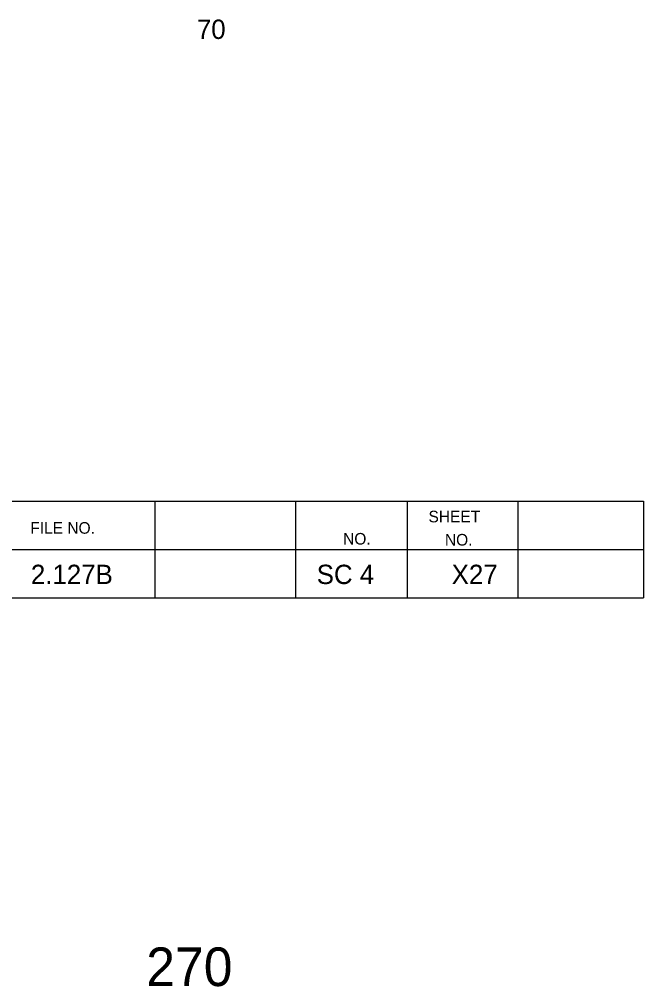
# Model space of a CAD drawing. Extents: x 1000 to 1162, y 999 to 8520.
# Drawn here: x 1145.41 to 1161.56, y 4079.99 to 4105.01 of the extents above; entities that cross this region are included whole.
import ezdxf

# ---------------------------------------------------------------- set-up
doc = ezdxf.new("R2010")
doc.units = 0
for name, color, linetype in [('Level 11', 7, 'Continuous'), ('Level 20', 7, 'Continuous'), ('Level 3', 7, 'Continuous'), ('Level 56', 7, 'Continuous')]:
    doc.layers.add(name, color=color, linetype=linetype)

msp = doc.modelspace()

# ---------------------------------------------------------------- linework, layer by layer
at = {"layer": 'Level 3'}
for p, q in [((1133.055, 4092.546), (1161.555, 4092.546)), ((1133.055, 4092.546), (1161.555, 4092.546)), ((1133.055, 4092.546), (1161.555, 4092.546)), ((1133.055, 4092.546), (1161.555, 4092.546)), ((1133.055, 4092.546), (1161.555, 4092.546)), ((1133.055, 4092.546), (1161.555, 4092.546)), ((1133.055, 4092.546), (1161.555, 4092.546)), ((1133.055, 4092.546), (1161.555, 4092.546)), ((1133.055, 4092.546), (1161.555, 4092.546)), ((1133.055, 4092.546), (1161.555, 4092.546)), ((1133.055, 4092.546), (1161.555, 4092.546)), ((1133.055, 4092.546), (1161.555, 4092.546)), ((1133.055, 4092.546), (1161.555, 4092.546)), ((1133.055, 4092.546), (1161.555, 4092.546)), ((1133.055, 4092.546), (1161.555, 4092.546)), ((1133.055, 4092.546), (1161.555, 4092.546)), ((1133.055, 4092.546), (1161.555, 4092.546)), ((1133.055, 4092.546), (1161.555, 4092.546)), ((1133.055, 4092.546), (1161.555, 4092.546)), ((1133.055, 4092.546), (1161.555, 4092.546)), ((1133.055, 4092.546), (1161.555, 4092.546)), ((1133.055, 4092.546), (1161.555, 4092.546)), ((1133.055, 4092.546), (1161.555, 4092.546)), ((1133.055, 4092.546), (1161.555, 4092.546)), ((1133.055, 4092.546), (1161.555, 4092.546)), ((1148.913, 4092.546), (1148.913, 4090.046)), ((1148.913, 4092.546), (1148.913, 4090.046)), ((1148.913, 4092.546), (1148.913, 4090.046)), ((1148.913, 4092.546), (1148.913, 4090.046)), ((1148.913, 4092.546), (1148.913, 4090.046)), ((1148.913, 4092.546), (1148.913, 4090.046)), ((1148.913, 4092.546), (1148.913, 4090.046)), ((1148.913, 4092.546), (1148.913, 4090.046)), ((1148.913, 4092.546), (1148.913, 4090.046)), ((1148.913, 4092.546), (1148.913, 4090.046)), ((1148.913, 4092.546), (1148.913, 4090.046)), ((1148.913, 4092.546), (1148.913, 4090.046)), ((1148.913, 4092.546), (1148.913, 4090.046)), ((1148.913, 4092.546), (1148.913, 4090.046)), ((1148.913, 4092.546), (1148.913, 4090.046)), ((1148.913, 4092.546), (1148.913, 4090.046)), ((1148.913, 4092.546), (1148.913, 4090.046)), ((1148.913, 4092.546), (1148.913, 4090.046)), ((1148.913, 4092.546), (1148.913, 4090.046)), ((1148.913, 4092.546), (1148.913, 4090.046)), ((1148.913, 4092.546), (1148.913, 4090.046)), ((1148.913, 4092.546), (1148.913, 4090.046)), ((1148.913, 4092.546), (1148.913, 4090.046)), ((1148.913, 4092.546), (1148.913, 4090.046)), ((1148.913, 4092.546), (1148.913, 4090.046)), ((1152.554, 4092.546), (1152.554, 4090.046)), ((1152.554, 4092.546), (1152.554, 4090.046)), ((1152.554, 4092.546), (1152.554, 4090.046)), ((1152.554, 4092.546), (1152.554, 4090.046)), ((1152.554, 4092.546), (1152.554, 4090.046)), ((1152.554, 4092.546), (1152.554, 4090.046)), ((1152.554, 4092.546), (1152.554, 4090.046)), ((1152.554, 4092.546), (1152.554, 4090.046)), ((1152.554, 4092.546), (1152.554, 4090.046)), ((1152.554, 4092.546), (1152.554, 4090.046)), ((1152.554, 4092.546), (1152.554, 4090.046)), ((1152.554, 4092.546), (1152.554, 4090.046)), ((1152.554, 4092.546), (1152.554, 4090.046)), ((1152.554, 4092.546), (1152.554, 4090.046)), ((1152.554, 4092.546), (1152.554, 4090.046)), ((1152.554, 4092.546), (1152.554, 4090.046)), ((1152.554, 4092.546), (1152.554, 4090.046)), ((1152.554, 4092.546), (1152.554, 4090.046)), ((1152.554, 4092.546), (1152.554, 4090.046)), ((1152.554, 4092.546), (1152.554, 4090.046)), ((1152.554, 4092.546), (1152.554, 4090.046)), ((1152.554, 4092.546), (1152.554, 4090.046)), ((1152.554, 4092.546), (1152.554, 4090.046)), ((1152.554, 4092.546), (1152.554, 4090.046)), ((1152.554, 4092.546), (1152.554, 4090.046)), ((1155.44, 4092.546), (1155.44, 4090.046)), ((1155.44, 4092.546), (1155.44, 4090.046)), ((1155.44, 4092.546), (1155.44, 4090.046)), ((1155.44, 4092.546), (1155.44, 4090.046)), ((1155.44, 4092.546), (1155.44, 4090.046)), ((1155.44, 4092.546), (1155.44, 4090.046)), ((1155.44, 4092.546), (1155.44, 4090.046)), ((1155.44, 4092.546), (1155.44, 4090.046)), ((1155.44, 4092.546), (1155.44, 4090.046)), ((1155.44, 4092.546), (1155.44, 4090.046)), ((1155.44, 4092.546), (1155.44, 4090.046)), ((1155.44, 4092.546), (1155.44, 4090.046)), ((1155.44, 4092.546), (1155.44, 4090.046)), ((1155.44, 4092.546), (1155.44, 4090.046)), ((1155.44, 4092.546), (1155.44, 4090.046)), ((1155.44, 4092.546), (1155.44, 4090.046)), ((1155.44, 4092.546), (1155.44, 4090.046)), ((1155.44, 4092.546), (1155.44, 4090.046)), ((1155.44, 4092.546), (1155.44, 4090.046)), ((1155.44, 4092.546), (1155.44, 4090.046)), ((1155.44, 4092.546), (1155.44, 4090.046)), ((1155.44, 4092.546), (1155.44, 4090.046)), ((1155.44, 4092.546), (1155.44, 4090.046)), ((1155.44, 4092.546), (1155.44, 4090.046)), ((1155.44, 4092.546), (1155.44, 4090.046)), ((1158.305, 4092.546), (1158.305, 4090.046)), ((1158.305, 4092.546), (1158.305, 4090.046)), ((1158.305, 4092.546), (1158.305, 4090.046)), ((1158.305, 4092.546), (1158.305, 4090.046)), ((1158.305, 4092.546), (1158.305, 4090.046)), ((1158.305, 4092.546), (1158.305, 4090.046)), ((1158.305, 4092.546), (1158.305, 4090.046)), ((1158.305, 4092.546), (1158.305, 4090.046)), ((1158.305, 4092.546), (1158.305, 4090.046)), ((1158.305, 4092.546), (1158.305, 4090.046)), ((1158.305, 4092.546), (1158.305, 4090.046)), ((1158.305, 4092.546), (1158.305, 4090.046)), ((1158.305, 4092.546), (1158.305, 4090.046)), ((1158.305, 4092.546), (1158.305, 4090.046)), ((1158.305, 4092.546), (1158.305, 4090.046)), ((1158.305, 4092.546), (1158.305, 4090.046)), ((1158.305, 4092.546), (1158.305, 4090.046)), ((1158.305, 4092.546), (1158.305, 4090.046)), ((1158.305, 4092.546), (1158.305, 4090.046)), ((1158.305, 4092.546), (1158.305, 4090.046)), ((1158.305, 4092.546), (1158.305, 4090.046)), ((1158.305, 4092.546), (1158.305, 4090.046)), ((1158.305, 4092.546), (1158.305, 4090.046)), ((1158.305, 4092.546), (1158.305, 4090.046)), ((1158.305, 4092.546), (1158.305, 4090.046)), ((1161.555, 4092.546), (1161.555, 4090.046)), ((1161.555, 4092.546), (1161.555, 4090.046)), ((1161.555, 4092.546), (1161.555, 4090.046)), ((1161.555, 4092.546), (1161.555, 4090.046)), ((1161.555, 4092.546), (1161.555, 4090.046)), ((1161.555, 4092.546), (1161.555, 4090.046)), ((1161.555, 4092.546), (1161.555, 4090.046)), ((1161.555, 4092.546), (1161.555, 4090.046)), ((1161.555, 4092.546), (1161.555, 4090.046)), ((1161.555, 4092.546), (1161.555, 4090.046)), ((1161.555, 4092.546), (1161.555, 4090.046)), ((1161.555, 4092.546), (1161.555, 4090.046)), ((1161.555, 4092.546), (1161.555, 4090.046)), ((1161.555, 4092.546), (1161.555, 4090.046)), ((1161.555, 4092.546), (1161.555, 4090.046)), ((1161.555, 4092.546), (1161.555, 4090.046)), ((1161.555, 4092.546), (1161.555, 4090.046)), ((1161.555, 4092.546), (1161.555, 4090.046)), ((1161.555, 4092.546), (1161.555, 4090.046)), ((1161.555, 4092.546), (1161.555, 4090.046)), ((1161.555, 4092.546), (1161.555, 4090.046)), ((1161.555, 4092.546), (1161.555, 4090.046)), ((1161.555, 4092.546), (1161.555, 4090.046)), ((1161.555, 4092.546), (1161.555, 4090.046)), ((1161.555, 4092.546), (1161.555, 4090.046)), ((1133.055, 4091.296), (1161.555, 4091.296)), ((1133.055, 4091.296), (1161.555, 4091.296)), ((1133.055, 4091.296), (1161.555, 4091.296)), ((1133.055, 4091.296), (1161.555, 4091.296)), ((1133.055, 4091.296), (1161.555, 4091.296)), ((1133.055, 4091.296), (1161.555, 4091.296)), ((1133.055, 4091.296), (1161.555, 4091.296)), ((1133.055, 4091.296), (1161.555, 4091.296)), ((1133.055, 4091.296), (1161.555, 4091.296)), ((1133.055, 4091.296), (1161.555, 4091.296)), ((1133.055, 4091.296), (1161.555, 4091.296)), ((1133.055, 4091.296), (1161.555, 4091.296)), ((1133.055, 4091.296), (1161.555, 4091.296)), ((1133.055, 4091.296), (1161.555, 4091.296)), ((1133.055, 4091.296), (1161.555, 4091.296)), ((1133.055, 4091.296), (1161.555, 4091.296)), ((1133.055, 4091.296), (1161.555, 4091.296)), ((1133.055, 4091.296), (1161.555, 4091.296)), ((1133.055, 4091.296), (1161.555, 4091.296)), ((1133.055, 4091.296), (1161.555, 4091.296)), ((1133.055, 4091.296), (1161.555, 4091.296)), ((1133.055, 4091.296), (1161.555, 4091.296)), ((1133.055, 4091.296), (1161.555, 4091.296)), ((1133.055, 4091.296), (1161.555, 4091.296)), ((1133.055, 4091.296), (1161.555, 4091.296)), ((1133.055, 4090.046), (1161.555, 4090.046)), ((1133.055, 4090.046), (1161.555, 4090.046)), ((1133.055, 4090.046), (1161.555, 4090.046)), ((1133.055, 4090.046), (1161.555, 4090.046)), ((1133.055, 4090.046), (1161.555, 4090.046)), ((1133.055, 4090.046), (1161.555, 4090.046)), ((1133.055, 4090.046), (1161.555, 4090.046)), ((1133.055, 4090.046), (1161.555, 4090.046)), ((1133.055, 4090.046), (1161.555, 4090.046)), ((1133.055, 4090.046), (1161.555, 4090.046)), ((1133.055, 4090.046), (1161.555, 4090.046)), ((1133.055, 4090.046), (1161.555, 4090.046)), ((1133.055, 4090.046), (1161.555, 4090.046)), ((1133.055, 4090.046), (1161.555, 4090.046)), ((1133.055, 4090.046), (1161.555, 4090.046)), ((1133.055, 4090.046), (1161.555, 4090.046)), ((1133.055, 4090.046), (1161.555, 4090.046)), ((1133.055, 4090.046), (1161.555, 4090.046)), ((1133.055, 4090.046), (1161.555, 4090.046)), ((1133.055, 4090.046), (1161.555, 4090.046)), ((1133.055, 4090.046), (1161.555, 4090.046)), ((1133.055, 4090.046), (1161.555, 4090.046)), ((1133.055, 4090.046), (1161.555, 4090.046)), ((1133.055, 4090.046), (1161.555, 4090.046)), ((1133.055, 4090.046), (1161.555, 4090.046))]:
    msp.add_line(p, q, dxfattribs=at)

# ---------------------------------------------------------------- texts
at = {"layer": 'Level 11'}
msp.add_text(' 270', height=1, dxfattribs=at).set_placement((1148.319, 4080))
at = {"layer": 'Level 20'}
for s, p in [('2.127B', (1145.707, 4090.4)), ('SC 4', (1153.099, 4090.4)), ('X27', (1156.59, 4090.4))]:
    msp.add_text(s, height=0.5, dxfattribs=at).set_placement(p)
at = {"layer": 'Level 3'}
for s, p in [('SHEET', (1155.99, 4091.996)), ('SHEET', (1155.99, 4091.996)), ('SHEET', (1155.99, 4091.996)), ('SHEET', (1155.99, 4091.996)), ('SHEET', (1155.99, 4091.996)), ('SHEET', (1155.99, 4091.996)), ('SHEET', (1155.99, 4091.996)), ('SHEET', (1155.99, 4091.996)), ('SHEET', (1155.99, 4091.996)), ('SHEET', (1155.99, 4091.996)), ('SHEET', (1155.99, 4091.996)), ('SHEET', (1155.99, 4091.996)), ('SHEET', (1155.99, 4091.996)), ('SHEET', (1155.99, 4091.996)), ('SHEET', (1155.99, 4091.996)), ('SHEET', (1155.99, 4091.996)), ('SHEET', (1155.99, 4091.996)), ('SHEET', (1155.99, 4091.996)), ('SHEET', (1155.99, 4091.996)), ('SHEET', (1155.99, 4091.996)), ('SHEET', (1155.99, 4091.996)), ('SHEET', (1155.99, 4091.996)), ('SHEET', (1155.99, 4091.996)), ('SHEET', (1155.99, 4091.996)), ('SHEET', (1155.99, 4091.996)), ('FILE NO.', (1145.691, 4091.702)), ('FILE NO.', (1145.691, 4091.702)), ('FILE NO.', (1145.691, 4091.702)), ('FILE NO.', (1145.691, 4091.702)), ('FILE NO.', (1145.691, 4091.702)), ('FILE NO.', (1145.691, 4091.702)), ('FILE NO.', (1145.691, 4091.702)), ('FILE NO.', (1145.691, 4091.702)), ('FILE NO.', (1145.691, 4091.702)), ('FILE NO.', (1145.691, 4091.702)), ('FILE NO.', (1145.691, 4091.702)), ('FILE NO.', (1145.691, 4091.702)), ('FILE NO.', (1145.691, 4091.702)), ('FILE NO.', (1145.691, 4091.702)), ('FILE NO.', (1145.691, 4091.702)), ('FILE NO.', (1145.691, 4091.702)), ('FILE NO.', (1145.691, 4091.702)), ('FILE NO.', (1145.691, 4091.702)), ('FILE NO.', (1145.691, 4091.702)), ('FILE NO.', (1145.691, 4091.702)), ('FILE NO.', (1145.691, 4091.702)), ('FILE NO.', (1145.691, 4091.702)), ('FILE NO.', (1145.691, 4091.702)), ('FILE NO.', (1145.691, 4091.702)), ('FILE NO.', (1145.691, 4091.702)), ('NO.', (1153.782, 4091.421)), ('NO.', (1153.782, 4091.421)), ('NO.', (1153.782, 4091.421)), ('NO.', (1153.782, 4091.421)), ('NO.', (1153.782, 4091.421)), ('NO.', (1153.782, 4091.421)), ('NO.', (1153.782, 4091.421)), ('NO.', (1153.782, 4091.421)), ('NO.', (1153.782, 4091.421)), ('NO.', (1153.782, 4091.421)), ('NO.', (1153.782, 4091.421)), ('NO.', (1153.782, 4091.421)), ('NO.', (1153.782, 4091.421)), ('NO.', (1153.782, 4091.421)), ('NO.', (1153.782, 4091.421)), ('NO.', (1153.782, 4091.421)), ('NO.', (1153.782, 4091.421)), ('NO.', (1153.782, 4091.421)), ('NO.', (1153.782, 4091.421)), ('NO.', (1153.782, 4091.421)), ('NO.', (1153.782, 4091.421)), ('NO.', (1153.782, 4091.421)), ('NO.', (1153.782, 4091.421)), ('NO.', (1153.782, 4091.421)), ('NO.', (1153.782, 4091.421)), ('NO.', (1156.415, 4091.396)), ('NO.', (1156.415, 4091.396)), ('NO.', (1156.415, 4091.396)), ('NO.', (1156.415, 4091.396)), ('NO.', (1156.415, 4091.396)), ('NO.', (1156.415, 4091.396)), ('NO.', (1156.415, 4091.396)), ('NO.', (1156.415, 4091.396)), ('NO.', (1156.415, 4091.396)), ('NO.', (1156.415, 4091.396)), ('NO.', (1156.415, 4091.396)), ('NO.', (1156.415, 4091.396)), ('NO.', (1156.415, 4091.396)), ('NO.', (1156.415, 4091.396)), ('NO.', (1156.415, 4091.396)), ('NO.', (1156.415, 4091.396)), ('NO.', (1156.415, 4091.396)), ('NO.', (1156.415, 4091.396)), ('NO.', (1156.415, 4091.396)), ('NO.', (1156.415, 4091.396)), ('NO.', (1156.415, 4091.396)), ('NO.', (1156.415, 4091.396)), ('NO.', (1156.415, 4091.396)), ('NO.', (1156.415, 4091.396)), ('NO.', (1156.415, 4091.396))]:
    msp.add_text(s, height=0.3, dxfattribs=at).set_placement(p)
at = {"layer": 'Level 56'}
msp.add_text('70', height=0.5, dxfattribs=at).set_placement((1150, 4104.5))

doc.saveas('drawing.dxf')
